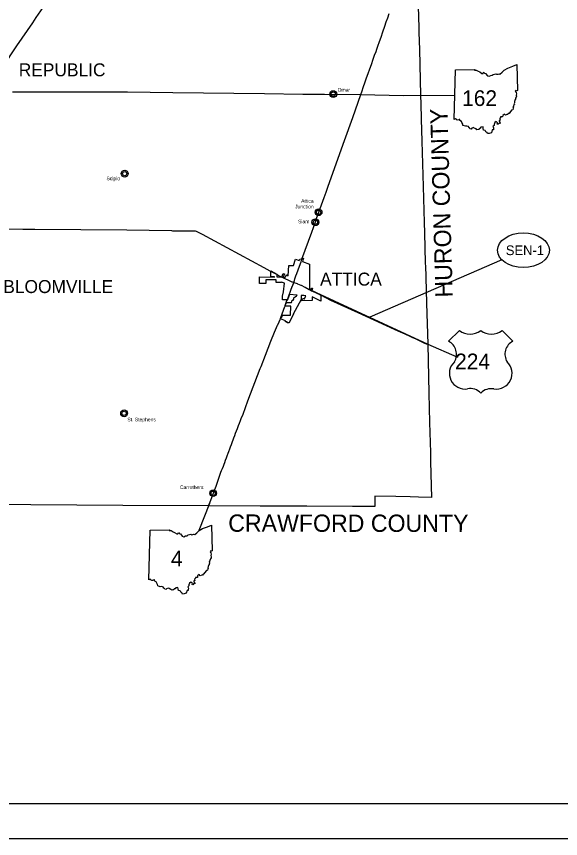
# Model space of a CAD drawing. Extents: x 0 to 882, y 0 to 440.
# Drawn here: x 427.4 to 584.7, y 0 to 237.6 of the extents above; entities that cross this region are included whole.
import ezdxf

# ---------------------------------------------------------------- set-up
doc = ezdxf.new("R2010")
doc.units = 0
for name, color, linetype in [('DV_X_Corp_Line', 7, 'Continuous'), ('GM_X_Adjacent_County_Text', 7, 'Continuous'), ('GM_X_Corporation_Text', 7, 'Continuous'), ('GM_X_County', 7, 'Continuous'), ('GM_X_State_Route', 7, 'Continuous'), ('GM_X_US_Route', 7, 'Continuous'), ('PV_P_Text', 7, 'Continuous'), ('RD_P_Fence', 7, 'Continuous'), ('SH_Border', 7, 'Continuous'), ('SH_Cut_Line', 7, 'Continuous'), ('SH_Data', 7, 'Continuous')]:
    doc.layers.add(name, color=color, linetype=linetype)

msp = doc.modelspace()

# ---------------------------------------------------------------- linework, layer by layer
at = {"layer": 'DV_X_Corp_Line'}
msp.add_lwpolyline([(509.68, 156.96), (509.68, 155.77), (507.37, 151.52), (507.51, 151.53), (506.26, 149.12), (506.26, 149.1), (506.25, 149.09), (506.23, 149.05), (505.67, 149.05), (505.67, 149.35), (505.19, 149.35), (505.19, 149.37), (505.19, 149.39), (505.19, 149.44), (505.19, 149.64), (503.77, 150.22), (503.92, 150.56), (503.98, 150.53), (504.17, 150.95), (504.27, 151.24), (504.28, 151.24), (504.29, 151.24), (504.31, 151.24), (504.36, 151.24), (506.66, 151.28), (506.72, 153.89), (505.23, 153.88), (505.19, 153.88), (505.14, 153.88), (505.09, 153.88), (505.03, 153.89), (505.08, 154.03), (505.09, 154.06), (505.38, 154.88), (506.86, 154.89), (507.12, 155.62), (507.43, 155.63), (507.54, 155.87), (507.57, 156.08), (507.61, 156.28), (507.65, 156.33), (507.68, 156.38), (507.87, 156.48), (507.93, 156.53), (508.35, 156.83), (508.55, 157.01), (506.29, 157.2), (505.73, 155.64), (504.27, 155.64), (504.29, 156.76), (504.62, 158.04), (504.86, 160.47), (503.97, 160.8), (503.99, 160.73), (502.5, 160.74), (502.5, 161.42), (499.52, 161.42), (499.52, 160.5), (499.52, 160.42), (497.63, 160.42), (497.64, 162.29), (501.97, 162.24), (501.97, 162.3), (500.9, 162.3), (500.9, 162.89), (500.9, 164.06), (502.65, 163.12), (502.69, 162.3), (503.56, 162.3), (503.85, 162.3), (504.11, 162.34), (504.48, 163.34), (504.85, 163.21), (504.45, 162.19), (504.91, 161.97), (505.56, 162.89), (505.91, 162.62), (506.09, 165.57), (507.51, 165.57), (508.04, 167.46), (509.16, 167.07), (509.32, 167.43), (510.04, 167.62), (510.41, 167.69), (510.2, 167.19), (510.19, 167.19), (510.05, 166.76), (512.13, 166.04), (512.14, 162.28), (512.07, 158.78), (512.51, 158.56), (512.77, 159.1), (512.95, 159.08), (512.81, 158.4), (513.49, 158.05), (515.42, 157.06), (515.42, 156.41), (515.42, 156.1), (515.4, 155.34), (512.86, 156.57), (512.89, 155.49), (509.82, 155.41), (510.17, 156.06), (510.63, 156.05), (510.6, 155.98), (510.66, 155.95), (510.92, 156.65), (511.02, 156.87), (510.5, 156.91)], close=True, dxfattribs=at)
for centre, radius in [((518.98, 215.15), 0.982), ((518.98, 215.15), 0.623), ((458.68, 192.15), 0.982), ((458.68, 192.15), 0.623), ((514.73, 181), 0.982), ((514.73, 181), 0.623), ((513.81, 178.12), 0.982), ((513.81, 178.12), 0.623), ((458.51, 122.89), 0.982), ((458.51, 122.89), 0.623), ((484.26, 99.81), 0.982), ((484.26, 99.81), 0.623)]:
    msp.add_circle(centre, radius, dxfattribs=at)
at = {"layer": 'GM_X_County'}
msp.add_lwpolyline([(543.13, 252.89), (543.68, 234.36), (543.71, 234.26), (543.74, 232.92), (543.87, 228.02), (544.18, 214.8), (544.25, 212.28), (544.38, 208.05), (544.38, 207.92), (544.57, 201.53), (544.97, 188.4), (545.28, 178.03), (545.37, 175.02), (545.58, 166.4), (545.59, 166.1), (545.61, 165.56), (545.72, 162.3), (545.72, 162.12), (545.97, 154.7), (546.29, 142.89), (546.64, 128.69), (546.84, 120.21), (547.05, 111.57), (547.11, 108.84), (547.35, 98.56), (543.65, 98.67), (541.24, 98.74), (537.08, 98.81), (530.99, 98.95), (530.98, 95.99), (524.66, 95.98), (524.5, 95.98), (511.34, 96.04), (511.14, 96.03), (498.02, 96.08), (497.84, 96.08), (482.9, 96.13), (458.13, 96.27), (444.84, 96.38), (431.55, 96.47), (418.34, 96.52)], dxfattribs=at)
at = {"layer": 'GM_X_State_Route'}
for p, q in [((544.18, 214.8), (554.14, 214.76)), ((546.29, 142.89), (554.66, 139.18)), ((483.21, 96.85), (480.11, 89.06))]:
    msp.add_line(p, q, dxfattribs=at)
for points in [[(423.36, 222.84), (427.54, 229.08), (432.09, 235.75), (433.12, 237.24), (441.18, 248.94), (446.03, 256.15), (446.36, 256.69), (446.66, 257.11), (447.13, 257.81), (449.99, 261.97), (452.05, 265.01), (454.26, 268.16), (454.83, 268.96), (457.29, 272.53), (459.34, 275.54), (460.09, 276.56), (460.6, 277.23), (461.17, 278), (463.6, 280.26), (465.54, 282.13), (471.41, 287.84)], [(526.9, 214.99), (527.03, 215.29), (527.21, 215.79), (527.75, 217.37), (528.13, 218.43), (528.62, 219.8), (529.07, 221.07), (529.54, 222.42), (530.01, 223.73), (530.52, 225.19), (530.94, 226.37), (531.34, 227.5), (531.55, 228.12), (531.87, 229.04), (532.32, 230.3), (532.78, 231.6), (533.33, 233.17), (533.87, 234.73), (534.3, 235.98), (534.73, 237.21), (535.14, 238.41)], [(426.21, 215.82), (432.91, 215.81), (446.37, 215.8)], [(446.37, 215.8), (446.37, 215.8), (459.54, 215.75), (472.62, 215.65), (499.07, 215.35), (510.14, 215.17), (512.52, 215.13), (516.41, 215.1), (526.9, 214.99)], [(515.2, 182.06), (516.35, 185.26), (516.93, 186.8), (517.52, 188.5), (522.24, 201.72), (524.59, 208.35), (526.9, 214.99)], [(526.9, 214.99), (539.14, 214.76), (544.18, 214.8)], [(509.92, 167.42), (509.93, 167.44), (512.75, 175.24), (513.7, 177.9), (514.07, 178.94), (514.17, 179.22), (515.2, 182.06)], [(508.18, 162.59), (508.43, 163.3), (508.83, 164.4), (509.19, 165.39), (509.66, 166.68)], [(509.66, 166.68), (509.66, 166.7), (509.92, 167.42)], [(507.54, 160.72), (507.73, 161.29), (507.86, 161.72)], [(507.86, 161.72), (507.87, 161.75), (507.88, 161.78), (508.18, 162.59)], [(506.11, 156.85), (506.12, 156.88), (506.6, 158.19), (506.7, 158.44), (507.1, 159.53), (507.13, 159.6)], [(507.13, 159.6), (507.13, 159.6), (507.15, 159.66), (507.54, 160.72)], [(505.6, 155.48), (505.61, 155.52), (506.11, 156.85)], [(504.97, 153.73), (505.03, 153.89), (505.08, 154.03), (505.09, 154.06), (505.33, 154.73)], [(505.33, 154.73), (505.38, 154.88), (505.6, 155.48)], [(503.77, 150.34), (503.86, 150.58), (504.97, 153.73)], [(502.9, 148.36), (502.96, 148.47), (503.33, 149.37), (503.62, 149.97)], [(503.62, 149.97), (503.7, 150.15), (503.72, 150.19), (503.77, 150.34)], [(482.9, 96.13), (483.21, 96.85), (483.58, 97.84), (483.84, 98.56), (484.06, 99.12), (484.16, 99.39), (484.32, 99.83), (484.43, 100.1), (484.63, 100.58), (484.73, 100.84), (485.11, 101.83), (485.66, 103.56), (485.88, 104.17), (486.08, 104.7), (486.29, 105.26), (486.51, 105.84), (486.69, 106.33), (486.94, 106.98), (487.2, 107.66), (487.41, 108.22), (487.6, 108.72), (487.84, 109.32), (488.08, 109.99), (488.31, 110.62), (488.59, 111.35), (488.8, 111.9), (489.09, 112.66), (489.31, 113.25), (489.54, 113.9), (489.85, 114.71), (490.05, 115.26), (490.27, 115.85), (490.49, 116.46), (490.75, 117.17), (490.99, 117.82), (491.25, 118.52), (491.57, 119.37), (491.83, 120.06), (492.12, 120.77), (492.4, 121.44), (492.91, 122.63), (494.33, 126.48), (497.89, 135.81), (498.11, 136.39), (499.43, 139.69), (500.97, 143.74), (501.97, 146.34), (502.9, 148.36)]]:
    msp.add_lwpolyline(points, dxfattribs=at)
at = {"layer": 'GM_X_US_Route'}
for points in [[(419.53, 176.16), (429.27, 176.1), (432.75, 176.11), (445.97, 176.05), (459.29, 175.89), (472.21, 175.68), (472.55, 175.67), (475.59, 175.64), (479.1, 175.58), (479.38, 175.51), (481.11, 174.68), (498.87, 165.03), (499.8, 164.54)], [(499.8, 164.54), (500.67, 164.09), (500.84, 164)], [(500.84, 164), (500.87, 163.98), (502.57, 163.07)], [(502.57, 163.07), (502.62, 163.04), (503.7, 162.46), (504.07, 162.28)], [(504.07, 162.28), (504.19, 162.23), (504.44, 162.11)], [(504.44, 162.11), (504.51, 162.08), (504.93, 161.88)], [(504.93, 161.88), (505, 161.85), (506, 161.38), (506.04, 161.36)], [(506.04, 161.36), (506.08, 161.34), (506.44, 161.17), (507, 160.93), (507.04, 160.92)], [(507.04, 160.92), (507.04, 160.91), (507.13, 160.88), (507.54, 160.72)], [(507.54, 160.72), (507.54, 160.72), (508.55, 160.37), (508.61, 160.35), (508.62, 160.34), (508.65, 160.33)], [(508.65, 160.33), (509.64, 159.91), (509.7, 159.88), (510.76, 159.34), (510.76, 159.33)], [(510.76, 159.33), (510.83, 159.3), (512.03, 158.68), (512.03, 158.68)], [(512.03, 158.68), (512.38, 158.5), (512.38, 158.5)], [(512.38, 158.5), (512.73, 158.33)], [(512.73, 158.33), (512.78, 158.3), (515.48, 157.02)], [(515.48, 157.02), (515.49, 157.02), (518.22, 155.58), (526.06, 152), (536.62, 147.2), (538.47, 146.37), (539.03, 146.13), (539.86, 145.74), (540.93, 145.26), (541.93, 144.8), (542.83, 144.37), (543.66, 144), (544.58, 143.57), (545.37, 143.21), (545.87, 143.01), (546.29, 142.89)]]:
    msp.add_lwpolyline(points, dxfattribs=at)
at = {"layer": 'PV_P_Text'}
for p, q in [((553.91, 207.81), (554.31, 222.18)), ((553.91, 207.81), (554.31, 222.18)), ((555.43, 146.82), (552.32, 143.71)), ((555.43, 146.82), (552.32, 143.71)), ((570.9, 143.71), (567.79, 146.82)), ((570.9, 143.71), (567.79, 146.82)), ((465.69, 74.74), (466.09, 89.1)), ((465.69, 74.74), (466.09, 89.1))]:
    msp.add_line(p, q, dxfattribs=at)
for points in [[(554.31, 222.18), (559.89, 222.27), (559.8, 222.1), (560.33, 222.06), (560.89, 221.75), (561.36, 221.56), (561.94, 221.1), (562.28, 221.11), (562.43, 221.48), (562.69, 221.19), (563.01, 221.14), (563.55, 220.45), (564, 220.31), (564.53, 220.54), (564.94, 220.58), (565.23, 220.81), (565.99, 221.01), (566.21, 220.89), (566.61, 220.92), (566.82, 221), (567.17, 220.93), (567.79, 221.45), (568.43, 222.06), (569.42, 222.64), (570.89, 223.2), (572.05, 223.69), (572.22, 216.23)], [(554.31, 222.18), (559.89, 222.27), (559.8, 222.1), (560.33, 222.06), (560.89, 221.75), (561.36, 221.56), (561.94, 221.1), (562.28, 221.11), (562.43, 221.48), (562.69, 221.19), (563.01, 221.14), (563.55, 220.45), (564, 220.31), (564.53, 220.54), (564.94, 220.58), (565.23, 220.81), (565.99, 221.01), (566.21, 220.89), (566.61, 220.92), (566.82, 221), (567.17, 220.93), (567.79, 221.45), (568.43, 222.06), (569.42, 222.64), (570.89, 223.2), (572.05, 223.69), (572.22, 216.23)], [(572.22, 216.23), (572.04, 216.13), (571.78, 216.18), (571.6, 215.97), (571.82, 215.62), (571.92, 215.25), (571.83, 214.85), (571.92, 214.51), (571.86, 214.23), (571.69, 213.95), (571.64, 213.69), (571.49, 213.41), (571.5, 213.25), (571.37, 213.12), (571.39, 212.66), (571.32, 212.4), (571.35, 212.18), (571.13, 212.12), (571.18, 211.93), (571.04, 211.79), (571.07, 211.55), (570.91, 211.39), (571.06, 211.08), (570.94, 210.98), (570.84, 210.6), (570.55, 210.52), (569.99, 209.83), (569.79, 209.56), (569.56, 209.5), (569.44, 209.23), (569.16, 209.23), (568.74, 209.04), (568.47, 209.36), (568, 208.97), (567.94, 208.53), (567.34, 208.54), (567.37, 208.31), (567.23, 208.25), (567.11, 208.02), (567.18, 207.62), (566.9, 207.52), (566.94, 207.28), (567.12, 207.14), (567.19, 206.69), (566.9, 206.78), (566.65, 206.41), (566.4, 206.49), (566.48, 206.81), (566.06, 207.2), (565.66, 206.89), (565.45, 206.4), (565.45, 206.07), (565.15, 205.87), (565.34, 205.4), (565.3, 205.08), (565.31, 204.77), (564.93, 204.78), (564.71, 203.96)], [(572.22, 216.23), (572.04, 216.13), (571.78, 216.18), (571.6, 215.97), (571.82, 215.62), (571.92, 215.25), (571.83, 214.85), (571.92, 214.51), (571.86, 214.23), (571.69, 213.95), (571.64, 213.69), (571.49, 213.41), (571.5, 213.25), (571.37, 213.12), (571.39, 212.66), (571.32, 212.4), (571.35, 212.18), (571.13, 212.12), (571.18, 211.93), (571.04, 211.79), (571.07, 211.55), (570.91, 211.39), (571.06, 211.08), (570.94, 210.98), (570.84, 210.6), (570.55, 210.52), (569.99, 209.83), (569.79, 209.56), (569.56, 209.5), (569.44, 209.23), (569.16, 209.23), (568.74, 209.04), (568.47, 209.36), (568, 208.97), (567.94, 208.53), (567.34, 208.54), (567.37, 208.31), (567.23, 208.25), (567.11, 208.02), (567.18, 207.62), (566.9, 207.52), (566.94, 207.28), (567.12, 207.14), (567.19, 206.69), (566.9, 206.78), (566.65, 206.41), (566.4, 206.49), (566.48, 206.81), (566.06, 207.2), (565.66, 206.89), (565.45, 206.4), (565.45, 206.07), (565.15, 205.87), (565.34, 205.4), (565.3, 205.08), (565.31, 204.77), (564.93, 204.78), (564.71, 203.96)], [(564.71, 203.96), (564.06, 203.8), (563.61, 203.71), (563.45, 204.08), (563.12, 204.28), (562.91, 204.66), (562.45, 204.71), (562.34, 205.23), (562.29, 205.65), (561.66, 205.54), (561.48, 205.29), (561.26, 205.22), (561.13, 204.96), (560.82, 204.94), (560.49, 204.81), (560.28, 205.07), (559.74, 205.32), (559.49, 205.45), (558.99, 205.25), (558.88, 205.01), (558.48, 205.11), (558.38, 205.38), (558.14, 205.47), (558.08, 205.75), (557.56, 205.9), (557.16, 205.84), (556.46, 206.07), (556.42, 206.45), (556.18, 206.91), (556.05, 207.23), (555.61, 207.47), (555.52, 207.85), (555.38, 207.84), (555.25, 207.68), (554.75, 207.61), (554.56, 207.77), (554.28, 208.03), (553.91, 207.81)], [(564.71, 203.96), (564.06, 203.8), (563.61, 203.71), (563.45, 204.08), (563.12, 204.28), (562.91, 204.66), (562.45, 204.71), (562.34, 205.23), (562.29, 205.65), (561.66, 205.54), (561.48, 205.29), (561.26, 205.22), (561.13, 204.96), (560.82, 204.94), (560.49, 204.81), (560.28, 205.07), (559.74, 205.32), (559.49, 205.45), (558.99, 205.25), (558.88, 205.01), (558.48, 205.11), (558.38, 205.38), (558.14, 205.47), (558.08, 205.75), (557.56, 205.9), (557.16, 205.84), (556.46, 206.07), (556.42, 206.45), (556.18, 206.91), (556.05, 207.23), (555.61, 207.47), (555.52, 207.85), (555.38, 207.84), (555.25, 207.68), (554.75, 207.61), (554.56, 207.77), (554.28, 208.03), (553.91, 207.81)], [(466.09, 89.1), (471.66, 89.2), (471.58, 89.02), (472.1, 88.99), (472.66, 88.68), (473.13, 88.49), (473.71, 88.03), (474.06, 88.04), (474.2, 88.41), (474.47, 88.12), (474.78, 88.07), (475.32, 87.38), (475.77, 87.23), (476.31, 87.47), (476.71, 87.51), (477, 87.74), (477.77, 87.94), (477.98, 87.82), (478.39, 87.84), (478.59, 87.93), (478.94, 87.85), (479.57, 88.38), (480.21, 88.99), (481.19, 89.57), (482.66, 90.12), (483.82, 90.61), (483.99, 83.16)], [(466.09, 89.1), (471.66, 89.2), (471.58, 89.02), (472.1, 88.99), (472.66, 88.68), (473.13, 88.49), (473.71, 88.03), (474.06, 88.04), (474.2, 88.41), (474.47, 88.12), (474.78, 88.07), (475.32, 87.38), (475.77, 87.23), (476.31, 87.47), (476.71, 87.51), (477, 87.74), (477.77, 87.94), (477.98, 87.82), (478.39, 87.84), (478.59, 87.93), (478.94, 87.85), (479.57, 88.38), (480.21, 88.99), (481.19, 89.57), (482.66, 90.12), (483.82, 90.61), (483.99, 83.16)], [(483.99, 83.16), (483.82, 83.06), (483.55, 83.11), (483.37, 82.9), (483.59, 82.55), (483.7, 82.18), (483.61, 81.77), (483.7, 81.44), (483.64, 81.16), (483.47, 80.88), (483.41, 80.61), (483.27, 80.33), (483.28, 80.18), (483.14, 80.05), (483.17, 79.59), (483.1, 79.33), (483.12, 79.1), (482.9, 79.05), (482.95, 78.86), (482.81, 78.72), (482.84, 78.47), (482.68, 78.32), (482.84, 78.01), (482.71, 77.91), (482.61, 77.53), (482.33, 77.45), (481.76, 76.75), (481.56, 76.49), (481.34, 76.43), (481.21, 76.16), (480.94, 76.15), (480.52, 75.97), (480.25, 76.29), (479.77, 75.9), (479.72, 75.45), (479.12, 75.47), (479.14, 75.24), (479.01, 75.18), (478.89, 74.95), (478.96, 74.55), (478.68, 74.44), (478.71, 74.21), (478.89, 74.07), (478.97, 73.62), (478.67, 73.71), (478.43, 73.33), (478.18, 73.42), (478.26, 73.74), (477.83, 74.12), (477.43, 73.82), (477.22, 73.33), (477.22, 72.99), (476.92, 72.79), (477.11, 72.33), (477.08, 72.01), (477.08, 71.7), (476.71, 71.71), (476.48, 70.89)], [(483.99, 83.16), (483.82, 83.06), (483.55, 83.11), (483.37, 82.9), (483.59, 82.55), (483.7, 82.18), (483.61, 81.77), (483.7, 81.44), (483.64, 81.16), (483.47, 80.88), (483.41, 80.61), (483.27, 80.33), (483.28, 80.18), (483.14, 80.05), (483.17, 79.59), (483.1, 79.33), (483.12, 79.1), (482.9, 79.05), (482.95, 78.86), (482.81, 78.72), (482.84, 78.47), (482.68, 78.32), (482.84, 78.01), (482.71, 77.91), (482.61, 77.53), (482.33, 77.45), (481.76, 76.75), (481.56, 76.49), (481.34, 76.43), (481.21, 76.16), (480.94, 76.15), (480.52, 75.97), (480.25, 76.29), (479.77, 75.9), (479.72, 75.45), (479.12, 75.47), (479.14, 75.24), (479.01, 75.18), (478.89, 74.95), (478.96, 74.55), (478.68, 74.44), (478.71, 74.21), (478.89, 74.07), (478.97, 73.62), (478.67, 73.71), (478.43, 73.33), (478.18, 73.42), (478.26, 73.74), (477.83, 74.12), (477.43, 73.82), (477.22, 73.33), (477.22, 72.99), (476.92, 72.79), (477.11, 72.33), (477.08, 72.01), (477.08, 71.7), (476.71, 71.71), (476.48, 70.89)], [(476.48, 70.89), (475.83, 70.73), (475.38, 70.63), (475.22, 71.01), (474.9, 71.21), (474.69, 71.58), (474.23, 71.64), (474.12, 72.15), (474.06, 72.57), (473.43, 72.47), (473.26, 72.21), (473.03, 72.14), (472.9, 71.88), (472.59, 71.86), (472.27, 71.74), (472.05, 71.99), (471.51, 72.25), (471.27, 72.38), (470.76, 72.18), (470.65, 71.94), (470.25, 72.04), (470.16, 72.31), (469.91, 72.39), (469.86, 72.68), (469.34, 72.83), (468.94, 72.77), (468.24, 73), (468.19, 73.38), (467.95, 73.84), (467.83, 74.15), (467.38, 74.4), (467.29, 74.78), (467.15, 74.76), (467.02, 74.61), (466.53, 74.54), (466.33, 74.7), (466.05, 74.96), (465.69, 74.74)], [(476.48, 70.89), (475.83, 70.73), (475.38, 70.63), (475.22, 71.01), (474.9, 71.21), (474.69, 71.58), (474.23, 71.64), (474.12, 72.15), (474.06, 72.57), (473.43, 72.47), (473.26, 72.21), (473.03, 72.14), (472.9, 71.88), (472.59, 71.86), (472.27, 71.74), (472.05, 71.99), (471.51, 72.25), (471.27, 72.38), (470.76, 72.18), (470.65, 71.94), (470.25, 72.04), (470.16, 72.31), (469.91, 72.39), (469.86, 72.68), (469.34, 72.83), (468.94, 72.77), (468.24, 73), (468.19, 73.38), (467.95, 73.84), (467.83, 74.15), (467.38, 74.4), (467.29, 74.78), (467.15, 74.76), (467.02, 74.61), (466.53, 74.54), (466.33, 74.7), (466.05, 74.96), (465.69, 74.74)]]:
    msp.add_lwpolyline(points, dxfattribs=at)
for centre, radius, start, end in [((558.52, 150.75), 5, 231.813, 308.187), ((558.52, 150.75), 5, 231.813, 308.187), ((564.7, 150.75), 5, 231.813, 308.187), ((564.7, 150.75), 5, 231.813, 308.187), ((550.37, 139.96), 4.23, 329.1175, 62.6108), ((550.37, 139.96), 4.23, 329.1175, 62.6108), ((572.84, 139.96), 4.23, 117.3892, 210.8825), ((572.84, 139.96), 4.23, 117.3892, 210.8825), ((557.11, 134.45), 4.56, 133.0046, 278.7282), ((557.11, 134.45), 4.56, 133.0046, 278.7282), ((566.1, 134.45), 4.56, 261.2718, 46.9954), ((566.1, 134.45), 4.56, 261.2718, 46.9954), ((558.64, 125.95), 4.08, 43.4177, 101.8742), ((558.64, 125.95), 4.08, 43.4177, 101.8742), ((564.66, 125.68), 4.33, 79.9613, 134.7468), ((564.66, 125.68), 4.33, 79.9613, 134.7468)]:
    msp.add_arc(centre, radius, start, end, dxfattribs=at)
at = {"layer": 'RD_P_Fence'}
msp.add_line((512.81, 158.4), (546.29, 142.89), dxfattribs=at)
at = {"layer": 'SH_Border'}
msp.add_lwpolyline([(30, 430), (670, 430), (670, 10), (30, 10)], close=True, dxfattribs=at)
at = {"layer": 'SH_Cut_Line'}
msp.add_lwpolyline([(0, 0), (680, 0), (680, 440), (0, 440)], close=True, dxfattribs=at)
at = {"layer": 'SH_Data'}
msp.add_line((567.67, 167.27), (529.55, 150.64), dxfattribs=at)
msp.add_ellipse((573.95, 170.01), major_axis=(7.5, 0), ratio=0.666667, dxfattribs=at)

# ---------------------------------------------------------------- texts
at = {"layer": 'DV_X_Corp_Line'}
for s, height, p in [('Omar', 1.042, (520.23, 215.86)), ('Scipio', 1.042, (453.43, 190.25)), ('Junction', 1.042, (507.95, 182.11)), ('Attica', 1.042, (509.69, 183.75)), ('Siam', 1.042, (508.8, 177.81)), ('St. Stephens', 1.0417, (459.46, 120.58)), ('Carrothers', 1.042, (474.65, 101.01))]:
    msp.add_text(s, height=height, rotation=0, dxfattribs=at).set_placement(p)
at = {"layer": 'GM_X_Adjacent_County_Text'}
for s, rotation, p in [('HURON COUNTY', 91.6554, (553.54, 156.43)), ('CRAWFORD COUNTY', 359.9592, (488.61, 88.66))]:
    msp.add_text(s, height=5, rotation=rotation, dxfattribs=at).set_placement(p)
at = {"layer": 'GM_X_Corporation_Text'}
for s, p in [('REPUBLIC', (428.06, 220.28)), ('ATTICA', (515.17, 159.8)), ('BLOOMVILLE', (423.59, 157.65))]:
    msp.add_text(s, height=3.75, rotation=0, dxfattribs=at).set_placement(p)
at = {"layer": 'PV_P_Text'}
for s, height, p in [('162', 4.528, (556.23, 211.71)), ('224', 4.528, (554.2, 135.63)), ('4', 4.53, (472.04, 78.64))]:
    msp.add_text(s, height=height, dxfattribs=at).set_placement(p)
at = {"layer": 'SH_Data'}
msp.add_text('SEN-1', height=2.8, dxfattribs=at).set_placement((568.86, 168.61))

doc.saveas('drawing.dxf')
